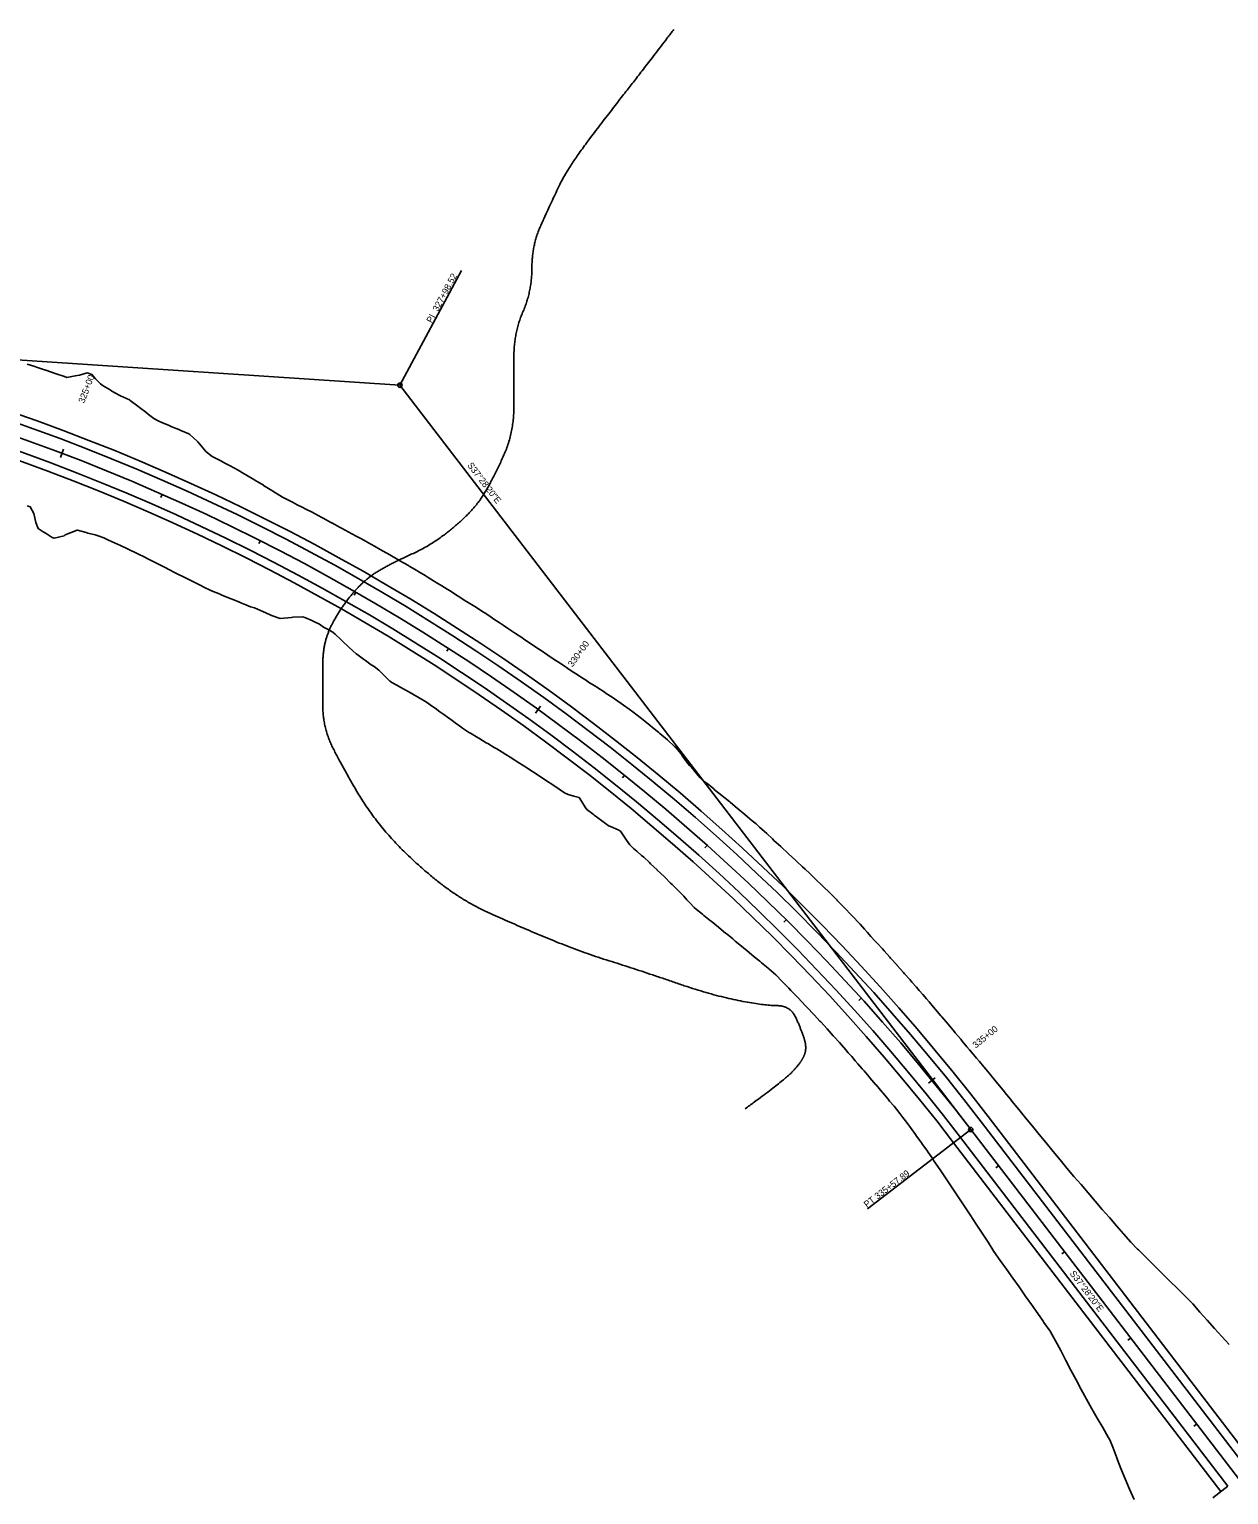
# Model space of a CAD drawing. Extents: x 881426 to 887360, y 1564404 to 1567430.
# Drawn here: x 882531 to 883637, y 1566079 to 1567430 of the extents above; entities that cross this region are included whole.
import ezdxf

# ---------------------------------------------------------------- set-up
doc = ezdxf.new("R2010")
doc.units = 0
for name, color, linetype in [('R_Erosion', 7, 'Continuous'), ('R_Horz Alg', 7, 'Continuous'), ('R_Horz Alg Annot', 7, 'Continuous'), ('R_Proposed Const Limits_Cut', 7, 'Continuous'), ('R_Proposed Const Limits_Fill', 7, 'Continuous'), ('R_Proposed Road_Lane', 7, 'Continuous'), ('R_Proposed Road_Shoulder', 7, 'Continuous')]:
    doc.layers.add(name, color=color, linetype=linetype)

msp = doc.modelspace()

# ---------------------------------------------------------------- linework, layer by layer
at = {"layer": 'R_Erosion'}
msp.add_open_spline([(883125.4, 1567430.4), (883099.6, 1567396.5), (883070.5, 1567359.4), (883027.7, 1567303.1), (883010.2, 1567266.2), (882994.5, 1567231.2), (882994.5, 1567188.7), (882977.9, 1567150.9), (882977.9, 1567104.8), (882977.9, 1567058.7), (882959.5, 1567017.1), (882941, 1566986.7), (882903.2, 1566955.3), (882866, 1566938.6), (882839.6, 1566923), (882815.7, 1566893.5), (882801.8, 1566864), (882801.8, 1566828), (882801.8, 1566785.9), (882820.7, 1566749), (882845.6, 1566706.5), (882880.6, 1566666.9), (882929.4, 1566627.2), (882982.9, 1566603.2), (883038.2, 1566580.2), (883097.2, 1566561.7), (883158.1, 1566540.5), (883207.8, 1566530.3), (883232.7, 1566530.3), (883242.9, 1566508.2), (883248.4, 1566490.6), (883242.4, 1566477.4), (883226.5, 1566460.8), (883191.2, 1566435.2)], degree=2, dxfattribs=at)
at = {"layer": 'R_Horz Alg'}
msp.add_line((883399.1, 1566415.9), (884332.7, 1565198), dxfattribs=at)
msp.add_arc((881883.4, 1565254), 1909.9, 37.4722, 86.2011, dxfattribs=at)
at = {"layer": 'R_Horz Alg Annot'}
for p, q in [((882009.9, 1567159.6), (882872.9, 1567102.3)), ((882872.9, 1567102.3), (883399.1, 1566415.9))]:
    msp.add_line(p, q, dxfattribs=at)
for points in [[(882872.9, 1567102.3), (882929.6, 1567208.1)], [(882562.7, 1567043.2), (882559.9, 1567035.7)], [(882652.6, 1566998.8), (882653.8, 1567001.5)], [(882742.8, 1566956.2), (882744.2, 1566958.8)], [(882830.8, 1566908.8), (882832.2, 1566911.4)], [(882916.1, 1566857), (882917.7, 1566859.5)], [(883002.6, 1566806.4), (882998, 1566799.9)], [(883078, 1566740.3), (883079.8, 1566742.6)], [(883154.1, 1566675.7), (883156.1, 1566677.9)], [(883226.8, 1566607.2), (883228.9, 1566609.4)], [(883295.8, 1566535.1), (883298, 1566537.1)], [(883366.3, 1566463.8), (883360.1, 1566458.8)], [(883399.1, 1566415.9), (883303.9, 1566342.9)], [(883422.3, 1566380.7), (883424.7, 1566382.5)], [(883483.2, 1566301.3), (883485.6, 1566303.1)], [(883544, 1566221.9), (883546.4, 1566223.7)], [(883604.9, 1566142.6), (883607.2, 1566144.4)]]:
    msp.add_lwpolyline(points, dxfattribs=at)
for centre in [(882872.9, 1567102.3), (883399.1, 1566415.9)]:
    msp.add_circle(centre, 2, dxfattribs=at)
at = {"layer": 'R_Proposed Const Limits_Cut'}
for points in [[(882811.1, 1566874.6), (882813.2, 1566872.7), (882818.5, 1566867.8), (882819.7, 1566866.7), (882825.7, 1566860.8), (882826, 1566860.5), (882832.5, 1566854.7), (882833.2, 1566854.2), (882839.4, 1566849.6), (882841.1, 1566848.5), (882846.4, 1566844.6), (882849, 1566842.8), (882853.3, 1566839.6), (882856.6, 1566836.6), (882859.6, 1566833.5), (882863.7, 1566829.5), (882866.1, 1566827.8), (882872.1, 1566824.6), (882873.6, 1566823.7), (882880.5, 1566819.8), (882881.1, 1566819.5), (882888.5, 1566815.3), (882889, 1566815), (882895.8, 1566810.9), (882897.3, 1566810), (882902.9, 1566806.1), (882905.3, 1566804.4), (882909.8, 1566801.1), (882913.2, 1566798.7), (882916.8, 1566796.2), (882921.1, 1566793), (882923.7, 1566791.1), (882928.9, 1566787.3), (882930.6, 1566786.1), (882937, 1566781.9), (882937.8, 1566781.5), (882945.1, 1566777.2), (882945.5, 1566777), (882952.5, 1566772.7), (882953.8, 1566771.9), (882959.8, 1566768.3), (882962.1, 1566766.9), (882967.1, 1566763.8), (882970.4, 1566761.8), (882974.4, 1566759.3), (882978.7, 1566756.6), (882981.7, 1566754.8), (882987, 1566751.4), (882988.9, 1566750.2), (882995.2, 1566746.1), (882996.1, 1566745.5), (883003.2, 1566740.8), (883003.3, 1566740.7), (883010.4, 1566736.1), (883011.5, 1566735.3), (883017.5, 1566731.3), (883019.6, 1566729.8), (883024.6, 1566726.4), (883028, 1566724.8), (883033.1, 1566723.4), (883038.2, 1566722)], [(883076.1, 1566691.1), (883079.8, 1566685.7), (883081.8, 1566682.7), (883084.9, 1566678.4), (883088.3, 1566675.2), (883091.2, 1566672.7), (883095.6, 1566668.8), (883097.7, 1566667), (883102.8, 1566662.2), (883103.9, 1566661.1), (883109.9, 1566655.5), (883110.1, 1566655.2), (883116.4, 1566649.4), (883117, 1566648.8), (883122.4, 1566643.3), (883123.8, 1566641.8), (883128.5, 1566637.2), (883130.8, 1566635), (883134.5, 1566631.1), (883137.5, 1566627.9), (883140.3, 1566624.8), (883144.2, 1566620.8), (883146.4, 1566618.8), (883151.7, 1566614.5), (883153.1, 1566613.4), (883159.3, 1566608.4), (883159.8, 1566608.1), (883166.4, 1566602.6), (883166.9, 1566602.2), (883173, 1566597.2), (883174.4, 1566596), (883179.7, 1566591.7), (883182, 1566589.8), (883186.3, 1566586.2), (883189.5, 1566583.6), (883192.9, 1566580.8), (883197.1, 1566577.3), (883199.5, 1566575.3), (883204.6, 1566571.1), (883206.2, 1566569.8), (883212.2, 1566564.8), (883212.8, 1566564.2), (883219.3, 1566558.6), (883219.6, 1566558.3), (883225.3, 1566552.5), (883226.4, 1566551.4), (883227.7, 1566550.1), (883231.3, 1566546.4), (883233.2, 1566544.3), (883237.2, 1566540.1), (883240, 1566537.3), (883243.2, 1566534), (883246.7, 1566530.2), (883249.1, 1566527.7), (883253.5, 1566523.1), (883255, 1566521.5), (883260.1, 1566515.9), (883260.8, 1566515.2), (883266.7, 1566508.9), (883266.8, 1566508.8), (883272.4, 1566502.5), (883273.3, 1566501.5), (883278.1, 1566496.1), (883279.8, 1566494.2), (883283.8, 1566489.6), (883286.2, 1566486.8), (883289.4, 1566483.2), (883292.6, 1566479.4), (883295, 1566476.7), (883299, 1566472), (883300.7, 1566470.2), (883305.4, 1566464.6), (883306.2, 1566463.6), (883311.7, 1566457.2), (883311.8, 1566457.1), (883317.3, 1566450.6), (883318.1, 1566449.7), (883322.9, 1566444), (883324.3, 1566442.2), (883328.4, 1566437.4), (883330.6, 1566434.7)]]:
    msp.add_lwpolyline(points, dxfattribs=at)
at = {"layer": 'R_Proposed Const Limits_Fill'}
for points in [[(882529.3, 1567121.8), (882536.3, 1567119.5), (882537.9, 1567119), (882546.2, 1567116.3), (882546.5, 1567116.1), (882555.1, 1567113.2), (882555.9, 1567112.9), (882563.7, 1567110.2), (882565.7, 1567109.5), (882573.6, 1567110.8), (882577.6, 1567111.6), (882584.5, 1567113.7), (882588.9, 1567112.2), (882592.2, 1567108.2), (882596.7, 1567103.4), (882599.4, 1567101.7), (882605.7, 1567097.9), (882607.3, 1567096.9), (882614.8, 1567092.8), (882615.4, 1567092.5), (882623.6, 1567088.7), (882624.1, 1567088.3), (882631.1, 1567082.9), (882632.7, 1567081.8), (882638.6, 1567077.3), (882641.2, 1567075.3), (882646, 1567071.5), (882649.9, 1567069.3), (882654.1, 1567067.5), (882659.4, 1567065.3), (882662.5, 1567064), (882668.9, 1567061.3), (882670.8, 1567060.4), (882678.4, 1567057.3), (882679.2, 1567056.9), (882686.3, 1567050.5), (882686.5, 1567050.2), (882692.7, 1567042.8), (882693.8, 1567041.3), (882699.7, 1567036.5), (882702.3, 1567035.3), (882707.7, 1567032.4), (882711.4, 1567030.4), (882715.7, 1567028.2), (882720.5, 1567025.7), (882723.7, 1567024), (882729.4, 1567020.5), (882731.4, 1567019.3), (882738.2, 1567015.2), (882739.2, 1567014.6), (882747, 1567010), (882747, 1567009.9), (882754.7, 1567005.3), (882755.8, 1567004.6), (882762.3, 1567000.5), (882764.5, 1566999.1), (882770.2, 1566996.2), (882773.7, 1566994.5), (882778.2, 1566992.1), (882782.8, 1566989.8), (882786.2, 1566988), (882791.9, 1566985.1), (882794.2, 1566983.9), (882800.9, 1566980.3), (882802.1, 1566979.7), (882809.9, 1566975.4), (882810, 1566975.4), (882817.9, 1566971.1), (882818.9, 1566970.5), (882825.8, 1566966.8), (882827.9, 1566965.7), (882833.7, 1566962.5), (882836.9, 1566960.8), (882841.6, 1566958.2), (882845.9, 1566955.8), (882849.5, 1566953.8), (882854.8, 1566950.8), (882857.3, 1566949.4), (882863.7, 1566945.8), (882865.1, 1566945), (882872.6, 1566940.7), (882872.9, 1566940.5), (882880.7, 1566935.9), (882881.4, 1566935.5), (882888.4, 1566931.4), (882890.2, 1566930.3), (882896.1, 1566926.7), (882899, 1566925), (882903.8, 1566922), (882907.7, 1566919.6), (882911.4, 1566917.3), (882916.4, 1566914.2), (882919.1, 1566912.6), (882925.1, 1566908.8), (882926.7, 1566907.8), (882933.7, 1566903.3), (882934.3, 1566903), (882941.8, 1566898.1), (882942.4, 1566897.8), (882949.4, 1566893.3), (882951, 1566892.3), (882956.9, 1566888.4), (882959.5, 1566886.7), (882964.4, 1566883.4), (882968.1, 1566881), (882971.9, 1566878.4), (882976.6, 1566875.3), (882979.4, 1566873.4), (882985.1, 1566869.6), (882986.9, 1566868.4), (882993.6, 1566863.9), (882994.3, 1566863.4), (883001.8, 1566858.4), (883002.1, 1566858.2), (883009.2, 1566853.3), (883010.5, 1566852.4), (883016.7, 1566848.4), (883019.1, 1566846.8), (883024.2, 1566843.4), (883027.7, 1566841.1), (883031.7, 1566838.4), (883036.2, 1566835.4), (883039.2, 1566833.5), (883044.8, 1566829.9), (883046.8, 1566828.6), (883053.5, 1566824.4), (883054.4, 1566823.8), (883062.1, 1566818.9), (883062.2, 1566818.8), (883069.6, 1566813.9), (883070.7, 1566813.1), (883076.9, 1566808.7), (883079.1, 1566807.2), (883084.3, 1566803.5), (883087.5, 1566801.2), (883091.6, 1566798.2), (883095.6, 1566795), (883098.6, 1566792.6), (883103.6, 1566788.5), (883105.6, 1566786.8), (883111.5, 1566782), (883112.5, 1566781.1), (883119.4, 1566775.4), (883119.5, 1566775.3), (883126.1, 1566769.2), (883126.9, 1566768.4), (883132.1, 1566762.4), (883133.5, 1566760.2), (883137.5, 1566754.7), (883139.7, 1566751.7), (883143.4, 1566747.8), (883146.6, 1566744), (883149.2, 1566740.7), (883153.7, 1566736.6), (883156, 1566734.9), (883161.8, 1566730.3), (883163, 1566729.3), (883169.7, 1566723.9), (883170, 1566723.7), (883177, 1566718), (883177.7, 1566717.4), (883183.9, 1566712.3), (883185.6, 1566710.9), (883190.8, 1566706.5), (883193.4, 1566704.3), (883197.7, 1566700.7), (883201.3, 1566697.8), (883204.5, 1566694.9), (883208.9, 1566690.9), (883211.2, 1566688.8), (883216.4, 1566683.9), (883217.7, 1566682.6), (883223.9, 1566677), (883224.4, 1566676.6), (883230.9, 1566670.5), (883231.4, 1566670), (883237.5, 1566664.3), (883238.8, 1566663), (883244, 1566658.1), (883246.3, 1566656), (883250.6, 1566652), (883253.7, 1566648.9), (883257.1, 1566645.7), (883261.2, 1566641.9), (883263.6, 1566639.6), (883268.6, 1566634.8), (883270.1, 1566633.3), (883275.8, 1566627.5), (883276.4, 1566626.9), (883282.7, 1566620.5), (883282.9, 1566620.2), (883288.9, 1566614), (883290, 1566612.8), (883291.3, 1566611.4), (883295, 1566607.4), (883297, 1566605.3), (883301.1, 1566600.8), (883303.9, 1566597.7), (883307.1, 1566594.1), (883310.8, 1566590.1), (883313.2, 1566587.5), (883317.6, 1566582.5), (883319.2, 1566580.8), (883324.4, 1566574.9), (883325.2, 1566574.1), (883331.2, 1566567.4), (883331.3, 1566567.3), (883337.1, 1566560.7), (883338.1, 1566559.6), (883343.1, 1566553.9), (883344.8, 1566552), (883349, 1566547.2), (883351.6, 1566544.3), (883354.9, 1566540.4), (883358.3, 1566536.5), (883360.8, 1566533.6), (883364.9, 1566528.7), (883366.6, 1566526.8), (883371.5, 1566520.9), (883372.4, 1566519.9), (883378.2, 1566513.1), (883378.2, 1566513.1), (883384, 1566506.1), (883384.7, 1566505.2), (883389.8, 1566499.3), (883391.3, 1566497.4), (883395.6, 1566492.4), (883397.9, 1566489.6), (883401.4, 1566485.6), (883404.5, 1566481.8), (883407.1, 1566478.7), (883411.1, 1566473.9), (883412.9, 1566471.8), (883417.6, 1566466), (883418.6, 1566464.8), (883424.1, 1566458.2), (883424.3, 1566457.9), (883430.1, 1566450.9), (883430.6, 1566450.2), (883435.7, 1566444), (883437.1, 1566442.3), (883443.4, 1566434.6), (883449.7, 1566426.8), (883456, 1566419.1), (883462.3, 1566411.3), (883468.7, 1566403.6), (883475, 1566395.8), (883481.4, 1566388.1), (883487.8, 1566380.4), (883494.2, 1566372.8), (883500.8, 1566365.2), (883507.3, 1566357.6), (883513.8, 1566350), (883520.3, 1566342.4), (883526.9, 1566334.8), (883533.4, 1566327.2), (883540, 1566319.7), (883546.6, 1566312.1), (883552.9, 1566305.8), (883553.7, 1566305), (883560.9, 1566297.9), (883568.1, 1566290.7), (883575.3, 1566283.7), (883582.4, 1566276.5), (883589.6, 1566269.5), (883596.8, 1566262.4), (883603.9, 1566255.2), (883610.4, 1566247.6), (883617, 1566240.1), (883623.7, 1566232.6), (883630.5, 1566225.2), (883637.3, 1566217.8)], [(882529.2, 1566991.2), (882532.1, 1566990), (882535.5, 1566983.9), (882537.1, 1566975.8), (882539.4, 1566970.1), (882544.1, 1566967.1), (882546.6, 1566965.5), (882552.4, 1566962), (882554.1, 1566961.4), (882563.4, 1566963.5), (882564.3, 1566964.2), (882575.2, 1566968.6), (882575.7, 1566968.5), (882583.5, 1566966.5), (882585.2, 1566966), (882591.8, 1566964.2), (882594.6, 1566963.5), (882599.9, 1566961.6), (882603.6, 1566959.8), (882607.6, 1566958), (882612.4, 1566955.8), (882615.4, 1566954.4), (882621.2, 1566951.6), (882623, 1566950.7), (882629.9, 1566947.5), (882630.7, 1566947.1), (882638.3, 1566943.3), (882638.6, 1566943.1), (882646, 1566939.5), (882647.3, 1566938.9), (882653.5, 1566935.7), (882655.9, 1566934.4), (882661.1, 1566931.6), (882664.5, 1566929.9), (882668.7, 1566927.9), (882673.3, 1566925.7), (882676.3, 1566924.1), (882681.9, 1566921.3), (882683.9, 1566920.3), (882690.6, 1566917), (882691.5, 1566916.5), (882699.1, 1566912.6), (882699.2, 1566912.6), (882707, 1566909.5), (882708.2, 1566909), (882714.9, 1566906.3), (882717.2, 1566905.4), (882722.8, 1566903.1), (882726.2, 1566901.7), (882730.7, 1566899.8), (882735.2, 1566898), (882738.8, 1566896.9), (882744.4, 1566894.6), (882746.6, 1566893.5), (882753.3, 1566890.7), (882754.4, 1566890), (882762.4, 1566887.1), (882762.5, 1566887.2), (882772.8, 1566888.2), (882774.1, 1566888.4), (882782.9, 1566888.7), (882785.2, 1566888.2), (882791, 1566885.8), (882794.1, 1566884.2), (882798.8, 1566882), (882802.5, 1566879.2), (882806, 1566877.4), (882811.1, 1566874.6)], [(883038.2, 1566722), (883040.3, 1566718.8), (883043.6, 1566713.1), (883045.2, 1566711), (883051, 1566706.7), (883052, 1566705.9), (883058.8, 1566700.8), (883058.9, 1566700.7), (883065.9, 1566695.8), (883067, 1566695.4), (883074.2, 1566692.4), (883076.1, 1566691.1)], [(883330.6, 1566434.7), (883333.8, 1566430.7), (883336.6, 1566427), (883339, 1566423.9), (883342.5, 1566419.2), (883344.1, 1566417), (883348.3, 1566411.3), (883349.1, 1566410), (883354, 1566403.3), (883354.1, 1566403), (883359.1, 1566396), (883359.6, 1566395.3), (883364, 1566389), (883365.2, 1566387.2), (883370.9, 1566379), (883376.5, 1566370.7), (883382.1, 1566362.4), (883387.6, 1566354), (883393.1, 1566345.7), (883398.6, 1566337.3), (883404.1, 1566328.9), (883409.6, 1566320.5), (883415.1, 1566312.1), (883420.5, 1566303.7), (883426.2, 1566295.4), (883432, 1566287.3), (883437.8, 1566279.1), (883443.6, 1566270.9), (883449.4, 1566262.8), (883455.1, 1566254.6), (883460.9, 1566246.4), (883465.9, 1566239.2), (883466.6, 1566238.2), (883472.4, 1566230), (883477.3, 1566221.2), (883482, 1566212.2), (883486.8, 1566203.2), (883491.5, 1566194.2), (883496.2, 1566185.3), (883501, 1566176.3), (883505.8, 1566167.4), (883510.6, 1566158.5), (883515.7, 1566149.8), (883520.8, 1566141.2), (883525.9, 1566132.4), (883527.4, 1566129.8), (883530, 1566123), (883533.7, 1566113.2), (883534.4, 1566111.4), (883537.6, 1566103.6), (883541.4, 1566093.9), (883545.3, 1566084.3), (883549.6, 1566075)]]:
    msp.add_lwpolyline(points, dxfattribs=at)
at = {"layer": 'R_Proposed Road_Lane'}
for p, q in [((883408.6, 1566423.2), (883655.1, 1566101.7)), ((883389.6, 1566408.6), (883636, 1566087.1)), ((883622.2, 1566076.4), (883636, 1566087.1))]:
    msp.add_line(p, q, dxfattribs=at)
for radius in [1921.9, 1897.9]:
    msp.add_arc((881883.4, 1565254), radius, 37.4722, 86.2011, dxfattribs=at)
at = {"layer": 'R_Proposed Road_Shoulder'}
for p, q in [((883415, 1566428.1), (883661.4, 1566106.5)), ((883383.2, 1566403.7), (883629.7, 1566082.2))]:
    msp.add_line(p, q, dxfattribs=at)
for radius in [1929.9, 1909.9, 1889.9]:
    msp.add_arc((881883.4, 1565254), radius, 37.4722, 86.2011, dxfattribs=at)

# ---------------------------------------------------------------- texts
at = {"layer": 'R_Horz Alg Annot'}
for s, rotation, p in [('PI  327+98.52', 61.8367, (882902.2, 1567159.1)), ('325+00', 69.2089, (882581.8, 1567085.2)), ('S37%%d28\'20"E', 307.4722, (882934.6, 1567028.3)), ('330+00', 54.2089, (883032, 1566842)), ('335+00', 39.2089, (883403.8, 1566490.6)), ('PT 335+57.89', 37.4722, (883303.3, 1566343.7)), ('S37%%d28\'20"E', 307.4722, (883490, 1566283.1))]:
    msp.add_text(s, height=6, rotation=rotation, dxfattribs=at).set_placement(p)

doc.saveas('drawing.dxf')
